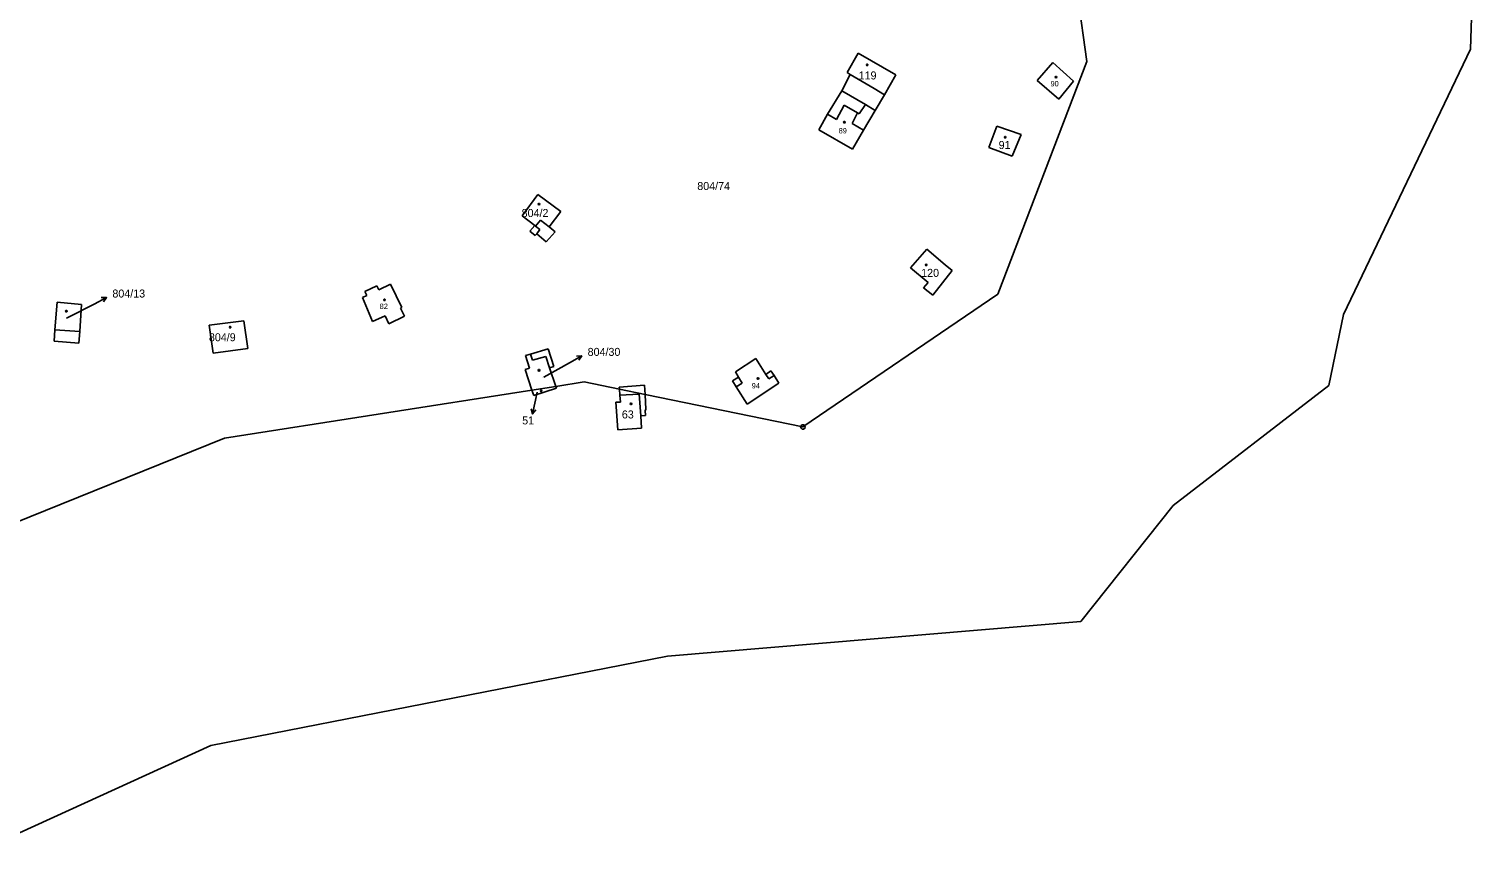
# Model space of a CAD drawing. Extents: x -845995 to -842497, y -1063614 to -1059680.
# Drawn here: x -843033.7 to -842725.2, y -1061954.9 to -1061782.5 of the extents above; entities that cross this region are included whole.
import ezdxf

# ---------------------------------------------------------------- set-up
doc = ezdxf.new("R2010")
doc.units = 0
for name, color, linetype in [('KN_HRANICE', 7, 'Continuous'), ('KN_KULTURY', 7, 'Continuous'), ('KN_MEZNIKY', 7, 'Continuous'), ('KN_PARCELY', 7, 'Continuous'), ('KN_SLUCKY', 7, 'Continuous'), ('KN_STAVEBNI', 7, 'Continuous')]:
    doc.layers.add(name, color=color, linetype=linetype)

# ---------------------------------------------------------------- blocks, each defined once
blk = doc.blocks.new('10292')
blk.add_line((0, 3), (0, 0))
blk.add_lwpolyline([(-0.5, 2), (0, 3), (0.5, 2)])
blk = doc.blocks.new('105')
blk.add_line((-0.12, 0), (0.12, 0))
blk.add_lwpolyline([(0.15, 0.48), (0.4, 0.3), (0.5, 0.01), (0.4, -0.28), (0.15, -0.46), (-0.16, -0.46), (-0.41, -0.28), (-0.51, 0.01), (-0.41, 0.3), (-0.16, 0.48), (0.15, 0.48)])
blk = doc.blocks.new('402')
blk.add_lwpolyline([(0.09, 0.15), (0.18, 0), (0.09, -0.15), (-0.09, -0.15), (-0.18, 0), (-0.09, 0.15), (0.09, 0.15)])

msp = doc.modelspace()

# ---------------------------------------------------------------- linework, layer by layer
at = {"layer": 'KN_HRANICE'}
for p, q in [((-842727.42, -1061786.81), (-842725.23, -1061707.32)), ((-842812.56, -1061763.55), (-842809, -1061789.41)), ((-842859.92, -1061791.76), (-842857.53, -1061787.68)), ((-842857.53, -1061787.68), (-842849.58, -1061792.29)), ((-842754.46, -1061843.22), (-842727.42, -1061786.81)), ((-842859.23, -1061792.17), (-842861.06, -1061795.66)), ((-842859.92, -1061791.76), (-842859.23, -1061792.17)), ((-842809, -1061789.41), (-842827.85, -1061838.93)), ((-842816.23, -1061789.64), (-842819.53, -1061793.48)), ((-842811.79, -1061793.62), (-842816.23, -1061789.64)), ((-842849.58, -1061792.29), (-842851.96, -1061796.5)), ((-842819.53, -1061793.48), (-842814.91, -1061797.46)), ((-842814.91, -1061797.46), (-842811.79, -1061793.62)), ((-842864.1, -1061800.63), (-842861.06, -1061795.66)), ((-842856.02, -1061798.6), (-842861.06, -1061795.66)), ((-842853.95, -1061799.81), (-842851.96, -1061796.5)), ((-842865.91, -1061803.94), (-842864.1, -1061800.63)), ((-842856.44, -1061804.05), (-842853.95, -1061799.81)), ((-842853.95, -1061799.81), (-842856.02, -1061798.6)), ((-842865.91, -1061803.94), (-842858.76, -1061808.04)), ((-842858.76, -1061808.04), (-842856.44, -1061804.05)), ((-842828.08, -1061803.14), (-842829.79, -1061807.73)), ((-842822.93, -1061804.98), (-842828.08, -1061803.14)), ((-842822.93, -1061804.98), (-842824.82, -1061809.55)), ((-842824.82, -1061809.55), (-842829.79, -1061807.73)), ((-842925.59, -1061817.74), (-842928.93, -1061822.21)), ((-842920.76, -1061821.35), (-842925.59, -1061817.74)), ((-842928.93, -1061822.21), (-842926.29, -1061824.29)), ((-842920.76, -1061821.35), (-842923.2, -1061824.61)), ((-842926.29, -1061824.29), (-842927.29, -1061825.53)), ((-842927.29, -1061825.53), (-842926.22, -1061826.43)), ((-842926.22, -1061826.43), (-842925.84, -1061826.04)), ((-842923.86, -1061827.76), (-842925.84, -1061826.04)), ((-842921.95, -1061825.61), (-842923.86, -1061827.76)), ((-842923.2, -1061824.61), (-842921.95, -1061825.61)), ((-842842.98, -1061829.35), (-842846.42, -1061833.31)), ((-842842.98, -1061829.35), (-842839.05, -1061832.65)), ((-842846.42, -1061833.31), (-842842.7, -1061836.45)), ((-842837.59, -1061833.85), (-842841.69, -1061839.11)), ((-842839.05, -1061832.65), (-842837.59, -1061833.85)), ((-842959.83, -1061837.13), (-842962.36, -1061838.36)), ((-842962.36, -1061838.36), (-842961.96, -1061839.17)), ((-842959.43, -1061837.94), (-842959.83, -1061837.13)), ((-842956.91, -1061836.77), (-842959.43, -1061837.94)), ((-842954.49, -1061841.75), (-842956.91, -1061836.77)), ((-842842.7, -1061836.45), (-842843.66, -1061837.58)), ((-842841.69, -1061839.11), (-842843.66, -1061837.58)), ((-843028.23, -1061846.45), (-843027.76, -1061840.62)), ((-843027.76, -1061840.62), (-843022.59, -1061841.06)), ((-843022.59, -1061841.06), (-843022.97, -1061846.83)), ((-842961.96, -1061839.17), (-842962.87, -1061839.61)), ((-842962.87, -1061839.61), (-842960.75, -1061844.7)), ((-842827.85, -1061838.93), (-842869.29, -1061867.13)), ((-842995.48, -1061845.52), (-842988.06, -1061844.57)), ((-842988.06, -1061844.57), (-842987.21, -1061850.43)), ((-842960.75, -1061844.7), (-842958.08, -1061843.48)), ((-842957.25, -1061845.18), (-842958.08, -1061843.48)), ((-842953.97, -1061843.57), (-842957.25, -1061845.18)), ((-842954.49, -1061841.75), (-842954.82, -1061841.9)), ((-842954.82, -1061841.9), (-842953.97, -1061843.57)), ((-842757.56, -1061858.35), (-842754.46, -1061843.22)), ((-843028.42, -1061848.92), (-843028.23, -1061846.45)), ((-843022.97, -1061846.83), (-843023.15, -1061849.34)), ((-842994.62, -1061851.42), (-842995.48, -1061845.52)), ((-843023.15, -1061849.34), (-843028.42, -1061848.92)), ((-842987.21, -1061850.43), (-842994.62, -1061851.42)), ((-842927.16, -1061851.63), (-842923.43, -1061850.52)), ((-842922.21, -1061854.25), (-842923.43, -1061850.52)), ((-842928.25, -1061851.95), (-842927.16, -1061851.63)), ((-842927.37, -1061854.6), (-842928.25, -1061851.95)), ((-842883.65, -1061855.4), (-842879.3, -1061852.61)), ((-842879.3, -1061852.61), (-842877.17, -1061855.98)), ((-842928.32, -1061854.92), (-842927.37, -1061854.6)), ((-842926.88, -1061859.29), (-842928.32, -1061854.92)), ((-842922.21, -1061854.25), (-842923.14, -1061854.56)), ((-842923.14, -1061854.56), (-842921.81, -1061858.5)), ((-842884.28, -1061857.33), (-842883, -1061856.51)), ((-842883, -1061856.51), (-842883.65, -1061855.4)), ((-842877.17, -1061855.98), (-842876.1, -1061855.22)), ((-842876.1, -1061855.22), (-842875.44, -1061856.21)), ((-842875.44, -1061856.21), (-842874.41, -1061857.84)), ((-842926.88, -1061859.29), (-842992.2, -1061869.51)), ((-842921.81, -1061858.5), (-842926.88, -1061859.29)), ((-842926.5, -1061860.45), (-842926.88, -1061859.29)), ((-842926.5, -1061860.45), (-842921.69, -1061858.86)), ((-842915.76, -1061857.55), (-842921.81, -1061858.5)), ((-842921.81, -1061858.5), (-842921.69, -1061858.86)), ((-842908.28, -1061859.09), (-842915.76, -1061857.55)), ((-842908.31, -1061858.66), (-842902.96, -1061858.27)), ((-842908.28, -1061859.09), (-842908.31, -1061858.66)), ((-842908.18, -1061860.4), (-842908.28, -1061859.09)), ((-842902.96, -1061858.27), (-842902.85, -1061860.21)), ((-842883.47, -1061858.61), (-842884.28, -1061857.33)), ((-842881.13, -1061862.32), (-842883.47, -1061858.61)), ((-842881.13, -1061862.32), (-842874.41, -1061857.84)), ((-842790.66, -1061883.86), (-842757.56, -1061858.35)), ((-842908.63, -1061867.76), (-842909.07, -1061861.89)), ((-842909.07, -1061861.89), (-842908.07, -1061861.89)), ((-842908.18, -1061860.4), (-842908.07, -1061861.89)), ((-842902.85, -1061860.21), (-842902.66, -1061863.44)), ((-842869.29, -1061867.13), (-842902.85, -1061860.21)), ((-842903.76, -1061864.77), (-842902.74, -1061864.69)), ((-842903.63, -1061867.4), (-842903.76, -1061864.77)), ((-842902.81, -1061863.62), (-842902.66, -1061863.44)), ((-842902.74, -1061864.69), (-842902.81, -1061863.62)), ((-842908.63, -1061867.76), (-842903.63, -1061867.4)), ((-842992.2, -1061869.51), (-843050.58, -1061893.1)), ((-842810.22, -1061908.5), (-842790.66, -1061883.86)), ((-842898.05, -1061915.85), (-842810.22, -1061908.5)), ((-842995.07, -1061934.86), (-842898.05, -1061915.85)), ((-843039.04, -1061954.95), (-842995.07, -1061934.86))]:
    msp.add_line(p, q, dxfattribs=at)
at = {"layer": 'KN_PARCELY'}
for p, q in [((-843025.75, -1061844.03), (-843019.92, -1061841)), ((-842924.32, -1061856.55), (-842918.89, -1061853.49)), ((-842925.75, -1061859.73), (-842926.11, -1061861.44))]:
    msp.add_line(p, q, dxfattribs=at)
at = {"layer": 'KN_SLUCKY'}
for p, q in [((-842859.23, -1061792.17), (-842854.17, -1061795.19)), ((-842854.17, -1061795.19), (-842851.96, -1061796.5)), ((-842864.1, -1061800.63), (-842862.17, -1061801.73)), ((-842862.17, -1061801.73), (-842860.54, -1061798.73)), ((-842857.68, -1061800.37), (-842860.54, -1061798.73)), ((-842857.68, -1061800.37), (-842858.84, -1061802.64)), ((-842857.38, -1061800.54), (-842857.68, -1061800.37)), ((-842856.02, -1061798.6), (-842857.38, -1061800.54)), ((-842858.84, -1061802.64), (-842856.44, -1061804.05)), ((-842926.09, -1061824.45), (-842926.29, -1061824.29)), ((-842925.06, -1061823.14), (-842926.09, -1061824.45)), ((-842925.2, -1061825.15), (-842926.09, -1061824.45)), ((-842925.84, -1061826.04), (-842925.2, -1061825.15)), ((-842923.2, -1061824.61), (-842925.06, -1061823.14)), ((-843022.97, -1061846.83), (-843028.23, -1061846.45)), ((-842926.77, -1061852.95), (-842927.16, -1061851.63)), ((-842923.95, -1061852.15), (-842926.77, -1061852.95)), ((-842923.95, -1061852.15), (-842923.14, -1061854.56)), ((-842883, -1061856.51), (-842882.19, -1061857.8)), ((-842877.17, -1061855.98), (-842876.57, -1061856.92)), ((-842876.57, -1061856.92), (-842875.44, -1061856.21)), ((-842902.85, -1061860.21), (-842908.28, -1061859.09)), ((-842882.19, -1061857.8), (-842883.47, -1061858.61)), ((-842904.07, -1061860.16), (-842908.18, -1061860.4)), ((-842903.76, -1061864.77), (-842904.07, -1061860.16))]:
    msp.add_line(p, q, dxfattribs=at)
at = {"layer": 'KN_STAVEBNI'}
for p, q in [((-842859.92, -1061791.76), (-842857.53, -1061787.68)), ((-842857.53, -1061787.68), (-842849.58, -1061792.29)), ((-842859.92, -1061791.76), (-842859.23, -1061792.17)), ((-842859.23, -1061792.17), (-842854.17, -1061795.19)), ((-842816.23, -1061789.64), (-842819.53, -1061793.48)), ((-842811.79, -1061793.62), (-842816.23, -1061789.64)), ((-842854.17, -1061795.19), (-842851.96, -1061796.5)), ((-842849.58, -1061792.29), (-842851.96, -1061796.5)), ((-842819.53, -1061793.48), (-842814.91, -1061797.46)), ((-842814.91, -1061797.46), (-842811.79, -1061793.62)), ((-842865.91, -1061803.94), (-842864.1, -1061800.63)), ((-842864.1, -1061800.63), (-842862.17, -1061801.73)), ((-842862.17, -1061801.73), (-842860.54, -1061798.73)), ((-842857.68, -1061800.37), (-842860.54, -1061798.73)), ((-842857.68, -1061800.37), (-842858.84, -1061802.64)), ((-842865.91, -1061803.94), (-842858.76, -1061808.04)), ((-842858.84, -1061802.64), (-842856.44, -1061804.05)), ((-842858.76, -1061808.04), (-842856.44, -1061804.05)), ((-842828.08, -1061803.14), (-842829.79, -1061807.73)), ((-842822.93, -1061804.98), (-842828.08, -1061803.14)), ((-842822.93, -1061804.98), (-842824.82, -1061809.55)), ((-842824.82, -1061809.55), (-842829.79, -1061807.73)), ((-842925.59, -1061817.74), (-842928.93, -1061822.21)), ((-842920.76, -1061821.35), (-842925.59, -1061817.74)), ((-842928.93, -1061822.21), (-842926.29, -1061824.29)), ((-842920.76, -1061821.35), (-842923.2, -1061824.61)), ((-842926.09, -1061824.45), (-842926.29, -1061824.29)), ((-842925.06, -1061823.14), (-842926.09, -1061824.45)), ((-842923.2, -1061824.61), (-842925.06, -1061823.14)), ((-842842.98, -1061829.35), (-842846.42, -1061833.31)), ((-842842.98, -1061829.35), (-842839.05, -1061832.65)), ((-842846.42, -1061833.31), (-842842.7, -1061836.45)), ((-842837.59, -1061833.85), (-842841.69, -1061839.11)), ((-842839.05, -1061832.65), (-842837.59, -1061833.85)), ((-842959.83, -1061837.13), (-842962.36, -1061838.36)), ((-842962.36, -1061838.36), (-842961.96, -1061839.17)), ((-842959.43, -1061837.94), (-842959.83, -1061837.13)), ((-842956.91, -1061836.77), (-842959.43, -1061837.94)), ((-842954.49, -1061841.75), (-842956.91, -1061836.77)), ((-842842.7, -1061836.45), (-842843.66, -1061837.58)), ((-842841.69, -1061839.11), (-842843.66, -1061837.58)), ((-843028.23, -1061846.45), (-843027.76, -1061840.62)), ((-843027.76, -1061840.62), (-843022.59, -1061841.06)), ((-843022.59, -1061841.06), (-843022.97, -1061846.83)), ((-842961.96, -1061839.17), (-842962.87, -1061839.61)), ((-842962.87, -1061839.61), (-842960.75, -1061844.7)), ((-842995.48, -1061845.52), (-842988.06, -1061844.57)), ((-842988.06, -1061844.57), (-842987.21, -1061850.43)), ((-842960.75, -1061844.7), (-842958.08, -1061843.48)), ((-842957.25, -1061845.18), (-842958.08, -1061843.48)), ((-842953.97, -1061843.57), (-842957.25, -1061845.18)), ((-842954.49, -1061841.75), (-842954.82, -1061841.9)), ((-842954.82, -1061841.9), (-842953.97, -1061843.57)), ((-843022.97, -1061846.83), (-843028.23, -1061846.45)), ((-842994.62, -1061851.42), (-842995.48, -1061845.52)), ((-842987.21, -1061850.43), (-842994.62, -1061851.42)), ((-842928.25, -1061851.95), (-842927.16, -1061851.63)), ((-842927.37, -1061854.6), (-842928.25, -1061851.95)), ((-842926.77, -1061852.95), (-842927.16, -1061851.63)), ((-842923.95, -1061852.15), (-842926.77, -1061852.95)), ((-842923.95, -1061852.15), (-842923.14, -1061854.56)), ((-842883.65, -1061855.4), (-842879.3, -1061852.61)), ((-842879.3, -1061852.61), (-842877.17, -1061855.98)), ((-842928.32, -1061854.92), (-842927.37, -1061854.6)), ((-842926.88, -1061859.29), (-842928.32, -1061854.92)), ((-842923.14, -1061854.56), (-842921.81, -1061858.5)), ((-842883, -1061856.51), (-842883.65, -1061855.4)), ((-842883, -1061856.51), (-842882.19, -1061857.8)), ((-842877.17, -1061855.98), (-842876.57, -1061856.92)), ((-842876.57, -1061856.92), (-842875.44, -1061856.21)), ((-842875.44, -1061856.21), (-842874.41, -1061857.84)), ((-842926.5, -1061860.45), (-842926.88, -1061859.29)), ((-842926.5, -1061860.45), (-842921.69, -1061858.86)), ((-842921.81, -1061858.5), (-842921.69, -1061858.86)), ((-842882.19, -1061857.8), (-842883.47, -1061858.61)), ((-842881.13, -1061862.32), (-842883.47, -1061858.61)), ((-842881.13, -1061862.32), (-842874.41, -1061857.84)), ((-842909.07, -1061861.89), (-842908.07, -1061861.89)), ((-842908.63, -1061867.76), (-842909.07, -1061861.89)), ((-842904.07, -1061860.16), (-842908.18, -1061860.4)), ((-842908.18, -1061860.4), (-842908.07, -1061861.89)), ((-842903.76, -1061864.77), (-842904.07, -1061860.16)), ((-842903.63, -1061867.4), (-842903.76, -1061864.77)), ((-842908.63, -1061867.76), (-842903.63, -1061867.4))]:
    msp.add_line(p, q, dxfattribs=at)

# ---------------------------------------------------------------- block references
at = {"layer": 'KN_KULTURY'}
for p in [(-842855.64, -1061790.16), (-842815.53, -1061792.74), (-842860.48, -1061802.35), (-842826.33, -1061805.53), (-842925.39, -1061819.74), (-842843.12, -1061832.68), (-842958.2, -1061840.12), (-843025.79, -1061842.52), (-842990.98, -1061845.91), (-842925.39, -1061855.09), (-842878.83, -1061856.82), (-842924.9, -1061859.45), (-842905.81, -1061862.2)]:
    msp.add_blockref('402', p, dxfattribs=at)
at = {"layer": 'KN_MEZNIKY'}
msp.add_blockref('105', (-842869.29, -1061867.13), dxfattribs=at)
at = {"layer": 'KN_PARCELY'}
for p, rotation in [((-843019.92, -1061841), -62.52031299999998), ((-842918.89, -1061853.49), -60.62955200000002), ((-842926.11, -1061861.44), 168.105817)]:
    msp.add_blockref('10292', p, dxfattribs=dict(at, rotation=rotation))

# ---------------------------------------------------------------- texts
for s, height, p in [('119', 1.7, (-842857.46, -1061793.24)), ('90', 1.14, (-842816.69, -1061794.71)), ('89', 1.14, (-842861.71, -1061804.72)), ('91', 1.7, (-842827.71, -1061808.03)), ('804/74', 1.7, (-842891.74, -1061816.75)), ('804/2', 1.7, (-842929.06, -1061822.49)), ('120', 1.7, (-842844.17, -1061835.22)), ('804/13', 1.7, (-843016.02, -1061839.61)), ('82', 1.14, (-842959.23, -1061842.05)), ('804/13', 0.1, (-843026.04, -1061844.03)), ('804/9', 1.7, (-842995.51, -1061848.91)), ('804/30', 1.7, (-842915.04, -1061852.02)), ('804/30', 0.1, (-842924.61, -1061856.55)), ('51', 0.1, (-842925.83, -1061859.73)), ('94', 1.14, (-842880.18, -1061858.94)), ('51', 1.7, (-842928.95, -1061866.59)), ('63', 1.7, (-842907.77, -1061865.32))]:
    msp.add_text(s, height=height, dxfattribs=at).set_placement(p)

doc.saveas('drawing.dxf')
